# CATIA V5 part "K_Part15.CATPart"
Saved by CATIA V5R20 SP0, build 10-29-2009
Part number: barre_2_bis
Bounding box of the stored display mesh (mm): x -16.009 to 2.493, y -1 to 0, z 41.001 to 52.493
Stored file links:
  G:\Khaled_CFAO_2011\ST2M\ST2M_GR2\gcausse\Khaled\CAD_ThinkMotion\K_Part15.CATPart
  C:\Documents and Settings\gcausse\Bureau\video thinkmotio\assemblage_gcausse\pupitre_think.CATProduct
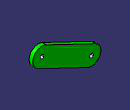
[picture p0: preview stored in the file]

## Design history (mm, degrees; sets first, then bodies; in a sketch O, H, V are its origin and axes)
Set1
  Sketch1 on Plane1, origin (0, 0, 0), H (-1, 0, 0), V (0, 0, 1)
    line L1 (14.6, 45.7467) -> (1.0843, 52.2526)
    arc A1 centre (0, 50) radius 2.5 from (1.0843, 52.2526) to (-1.0843, 47.7474) ccw
    point P3 (0, 50)
    line L2 (-1.0843, 47.7474) -> (12.4313, 41.2415)
    arc A2 centre (13.5157, 43.4941) radius 2.5 from (12.4313, 41.2415) to (14.6, 45.7467) ccw
    point P6 (13.5157, 43.4941)
    reference projected point E1 (0, 50) from Point1
    reference projected point E2 (13.5157, 43.4941) from Point2
    reference projected line E3 (0, 50) -> (13.5157, 43.4941) from Line1
    distance L1 L2 = 5
    tangency: A1 L1, L2 A1, A2 L1, A2 L2
    coincidence: P3 E1, P6 E2
    parallelism: L1 E3
Set2
  Plane1: linked copy from another document
  Point1: linked copy from another document
  Point2: linked copy from another document
  Line1: linked copy from another document
Body1 (main body)
  Pad1: profile Sketch1, direction (0, -1, 0), length 1
  Sketch2 on start face of Pad1, origin (-3.0891, 0, 50.1764), H (1, 0, 0), V (0, 0, -1)
    point P1 (3.0891, 0.1764)
    reference projected point E1 (3.0891, 0.1764) from Point1
    coincidence: P1 E1
  Hole1: placed by Sketch2, at (0, 0, 50) direction (0, -1, 0), diameter 1, depth 1
  Sketch3 on start face of Pad1, origin (-10.9739, 0, 45.9834), H (1, 0, 0), V (0, 0, -1)
    point P1 (-2.5418, 2.4893)
    reference projected point E1 (-2.5418, 2.4893) from Point2
    coincidence: E1 P1
  Hole2: placed by Sketch3, at (-13.5157, 0, 43.4941) direction (0, -1, 0), diameter 1, depth 1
